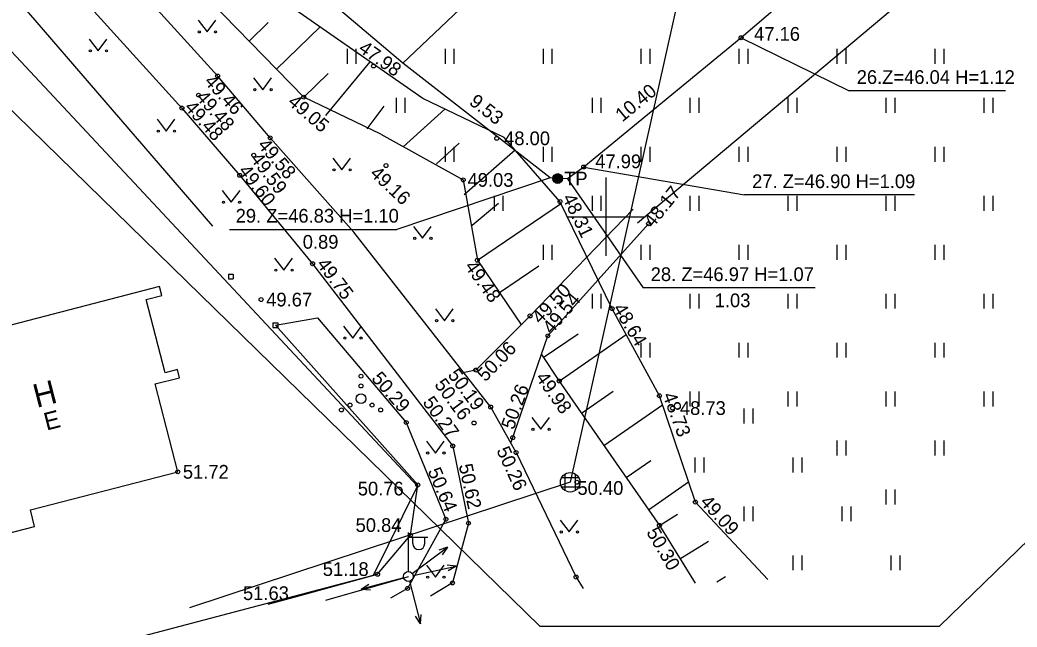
# Model space of a CAD drawing. Extents: x 642747 to 644424, y 6457048 to 6458238.
# Drawn here: x 644020.1 to 644071, y 6457529.1 to 6457560 of the extents above; entities that cross this region are included whole.
import ezdxf

# ---------------------------------------------------------------- set-up
doc = ezdxf.new("R2010")
doc.units = 0
for name, color, linetype in [('AED', 7, 'Continuous'), ('DKAEV', 7, 'Continuous'), ('DTRASS', 7, 'Continuous'), ('HALJASTUS', 7, 'Continuous'), ('HOONE', 7, 'Continuous'), ('JOONSIDE', 7, 'Continuous'), ('KOORDPUNKT', 7, 'Continuous'), ('KORGUS', 7, 'Continuous'), ('KPKAABEL', 7, 'Continuous'), ('MOOTPIIR', 7, 'Continuous'), ('MPOHULIIN', 7, 'Continuous'), ('PIIR', 7, 'Continuous'), ('POST', 7, 'Continuous'), ('RELJEEF', 7, 'Continuous'), ('TEE', 7, 'Continuous'), ('VORK', 7, 'Continuous')]:
    doc.layers.add(name, color=color, linetype=linetype)

msp = doc.modelspace()

# ---------------------------------------------------------------- linework, layer by layer
at = {"layer": 'AED'}
for p, q in [((644030.734, 6457547.073), (644030.734, 6457546.823)), ((644030.734, 6457547.073), (644030.984, 6457547.073)), ((644030.984, 6457547.073), (644030.984, 6457546.823)), ((644030.734, 6457546.823), (644030.984, 6457546.823)), ((644033.01, 6457544.59), (644033.01, 6457544.34)), ((644033.01, 6457544.59), (644033.26, 6457544.59)), ((644033.26, 6457544.59), (644033.26, 6457544.34)), ((644033.01, 6457544.34), (644033.26, 6457544.34))]:
    msp.add_line(p, q, dxfattribs=at)
for points in [[(644038.347, 6457531.745), (644040.021, 6457533.742), (644040.399, 6457536.307), (644033.135, 6457544.465)], [(644032.769, 6457530.227), (644034.097, 6457530.581), (644038.347, 6457531.745)]]:
    msp.add_lwpolyline(points, dxfattribs=at)
at = {"layer": 'DKAEV'}
for p, q in [((644047.925, 6457536.009), (644047.925, 6457536.875)), ((644048.425, 6457536.875), (644048.425, 6457536.009)), ((644047.742, 6457536.692), (644048.608, 6457536.692)), ((644048.608, 6457536.192), (644047.742, 6457536.192))]:
    msp.add_line(p, q, dxfattribs=at)
msp.add_circle((644048.175, 6457536.442), 0.5, dxfattribs=at)
at = {"layer": 'DTRASS'}
for points in [[(644054.394, 6457564.336), (644048.175, 6457536.442)], [(644048.175, 6457536.442), (644028.741, 6457530.029)]]:
    msp.add_lwpolyline(points, dxfattribs=at)
at = {"layer": 'HALJASTUS'}
for p, q in [((644029.185, 6457560.042), (644029.648, 6457559.436)), ((644029.648, 6457559.436), (644030.094, 6457560.042)), ((644023.626, 6457559.073), (644024.09, 6457558.466)), ((644024.09, 6457558.466), (644024.535, 6457559.073)), ((644036.79, 6457558.569), (644036.79, 6457557.807)), ((644037.245, 6457558.569), (644037.245, 6457557.807)), ((644041.79, 6457558.569), (644041.79, 6457557.807)), ((644042.245, 6457558.569), (644042.245, 6457557.807)), ((644046.79, 6457558.569), (644046.79, 6457557.807)), ((644047.245, 6457558.569), (644047.245, 6457557.807)), ((644051.79, 6457558.569), (644051.79, 6457557.807)), ((644052.245, 6457558.569), (644052.245, 6457557.807)), ((644056.79, 6457558.569), (644056.79, 6457557.807)), ((644057.245, 6457558.569), (644057.245, 6457557.807)), ((644061.79, 6457558.569), (644061.79, 6457557.807)), ((644062.245, 6457558.569), (644062.245, 6457557.807)), ((644066.79, 6457558.569), (644066.79, 6457557.807)), ((644067.245, 6457558.569), (644067.245, 6457557.807)), ((644032.022, 6457557.094), (644032.486, 6457556.487)), ((644032.486, 6457556.487), (644032.931, 6457557.094)), ((644039.29, 6457556.069), (644039.29, 6457555.307)), ((644039.745, 6457556.069), (644039.745, 6457555.307)), ((644049.29, 6457556.069), (644049.29, 6457555.307)), ((644049.745, 6457556.069), (644049.745, 6457555.307)), ((644054.29, 6457556.069), (644054.29, 6457555.307)), ((644054.745, 6457556.069), (644054.745, 6457555.307)), ((644059.29, 6457556.069), (644059.29, 6457555.307)), ((644059.745, 6457556.069), (644059.745, 6457555.307)), ((644064.29, 6457556.069), (644064.29, 6457555.307)), ((644064.745, 6457556.069), (644064.745, 6457555.307)), ((644069.29, 6457556.069), (644069.29, 6457555.307)), ((644069.745, 6457556.069), (644069.745, 6457555.307)), ((644027.092, 6457554.977), (644027.555, 6457554.37)), ((644027.555, 6457554.37), (644028.001, 6457554.977)), ((644041.79, 6457553.569), (644041.79, 6457552.807)), ((644042.245, 6457553.569), (644042.245, 6457552.807)), ((644046.79, 6457553.569), (644046.79, 6457552.807)), ((644047.245, 6457553.569), (644047.245, 6457552.807)), ((644051.79, 6457553.569), (644051.79, 6457552.807)), ((644052.245, 6457553.569), (644052.245, 6457552.807)), ((644056.79, 6457553.569), (644056.79, 6457552.807)), ((644057.245, 6457553.569), (644057.245, 6457552.807)), ((644061.79, 6457553.569), (644061.79, 6457552.807)), ((644062.245, 6457553.569), (644062.245, 6457552.807)), ((644066.79, 6457553.569), (644066.79, 6457552.807)), ((644067.245, 6457553.569), (644067.245, 6457552.807)), ((644036.061, 6457552.998), (644036.524, 6457552.391)), ((644036.524, 6457552.391), (644036.97, 6457552.998)), ((644030.421, 6457551.346), (644030.884, 6457550.739)), ((644030.884, 6457550.739), (644031.33, 6457551.346)), ((644044.29, 6457551.069), (644044.29, 6457550.307)), ((644044.745, 6457551.069), (644044.745, 6457550.307)), ((644049.29, 6457551.069), (644049.29, 6457550.307)), ((644049.745, 6457551.069), (644049.745, 6457550.307)), ((644054.29, 6457551.069), (644054.29, 6457550.307)), ((644054.745, 6457551.069), (644054.745, 6457550.307)), ((644059.29, 6457551.069), (644059.29, 6457550.307)), ((644059.745, 6457551.069), (644059.745, 6457550.307)), ((644064.29, 6457551.069), (644064.29, 6457550.307)), ((644064.745, 6457551.069), (644064.745, 6457550.307)), ((644069.29, 6457551.069), (644069.29, 6457550.307)), ((644069.745, 6457551.069), (644069.745, 6457550.307)), ((644040.181, 6457549.503), (644040.645, 6457548.897)), ((644040.645, 6457548.897), (644041.09, 6457549.503)), ((644046.79, 6457548.569), (644046.79, 6457547.807)), ((644047.245, 6457548.569), (644047.245, 6457547.807)), ((644051.79, 6457548.569), (644051.79, 6457547.807)), ((644052.245, 6457548.569), (644052.245, 6457547.807)), ((644056.79, 6457548.569), (644056.79, 6457547.807)), ((644057.245, 6457548.569), (644057.245, 6457547.807)), ((644061.79, 6457548.569), (644061.79, 6457547.807)), ((644062.245, 6457548.569), (644062.245, 6457547.807)), ((644066.79, 6457548.569), (644066.79, 6457547.807)), ((644067.245, 6457548.569), (644067.245, 6457547.807)), ((644033.095, 6457547.878), (644033.558, 6457547.272)), ((644033.558, 6457547.272), (644034.004, 6457547.878)), ((644049.29, 6457546.069), (644049.29, 6457545.307)), ((644049.745, 6457546.069), (644049.745, 6457545.307)), ((644054.29, 6457546.069), (644054.29, 6457545.307)), ((644054.745, 6457546.069), (644054.745, 6457545.307)), ((644059.29, 6457546.069), (644059.29, 6457545.307)), ((644059.745, 6457546.069), (644059.745, 6457545.307)), ((644064.29, 6457546.069), (644064.29, 6457545.307)), ((644064.745, 6457546.069), (644064.745, 6457545.307)), ((644069.29, 6457546.069), (644069.29, 6457545.307)), ((644069.745, 6457546.069), (644069.745, 6457545.307)), ((644041.3, 6457545.299), (644041.764, 6457544.692)), ((644041.764, 6457544.692), (644042.209, 6457545.299)), ((644036.615, 6457544.411), (644037.078, 6457543.804)), ((644037.078, 6457543.804), (644037.524, 6457544.411)), ((644051.79, 6457543.569), (644051.79, 6457542.807)), ((644052.245, 6457543.569), (644052.245, 6457542.807)), ((644056.79, 6457543.569), (644056.79, 6457542.807)), ((644057.245, 6457543.569), (644057.245, 6457542.807)), ((644061.79, 6457543.569), (644061.79, 6457542.807)), ((644062.245, 6457543.569), (644062.245, 6457542.807)), ((644066.79, 6457543.569), (644066.79, 6457542.807)), ((644067.245, 6457543.569), (644067.245, 6457542.807)), ((644054.29, 6457541.069), (644054.29, 6457540.307)), ((644054.745, 6457541.069), (644054.745, 6457540.307)), ((644059.29, 6457541.069), (644059.29, 6457540.307)), ((644059.745, 6457541.069), (644059.745, 6457540.307)), ((644064.29, 6457541.069), (644064.29, 6457540.307)), ((644064.745, 6457541.069), (644064.745, 6457540.307)), ((644069.29, 6457541.069), (644069.29, 6457540.307)), ((644069.745, 6457541.069), (644069.745, 6457540.307)), ((644057.043, 6457540.21), (644057.043, 6457539.449)), ((644057.498, 6457540.21), (644057.498, 6457539.449)), ((644046.212, 6457539.756), (644046.675, 6457539.149)), ((644046.675, 6457539.149), (644047.121, 6457539.756)), ((644040.844, 6457538.541), (644041.308, 6457537.934)), ((644041.308, 6457537.934), (644041.753, 6457538.541)), ((644061.79, 6457538.569), (644061.79, 6457537.807)), ((644062.245, 6457538.569), (644062.245, 6457537.807)), ((644066.79, 6457538.569), (644066.79, 6457537.807)), ((644067.245, 6457538.569), (644067.245, 6457537.807)), ((644054.543, 6457537.71), (644054.543, 6457536.949)), ((644054.998, 6457537.71), (644054.998, 6457536.949)), ((644059.543, 6457537.71), (644059.543, 6457536.949)), ((644059.998, 6457537.71), (644059.998, 6457536.949)), ((644064.29, 6457536.069), (644064.29, 6457535.307)), ((644064.745, 6457536.069), (644064.745, 6457535.307)), ((644057.043, 6457535.21), (644057.043, 6457534.449)), ((644057.498, 6457535.21), (644057.498, 6457534.449)), ((644062.043, 6457535.21), (644062.043, 6457534.449)), ((644062.498, 6457535.21), (644062.498, 6457534.449)), ((644047.658, 6457534.514), (644048.121, 6457533.907)), ((644048.121, 6457533.907), (644048.567, 6457534.514)), ((644059.543, 6457532.71), (644059.543, 6457531.949)), ((644059.998, 6457532.71), (644059.998, 6457531.949)), ((644064.543, 6457532.71), (644064.543, 6457531.949)), ((644064.998, 6457532.71), (644064.998, 6457531.949)), ((644040.844, 6457532.206), (644041.308, 6457531.6)), ((644041.308, 6457531.6), (644041.753, 6457532.206))]:
    msp.add_line(p, q, dxfattribs=at)
for points in [[(643947.897, 6457637.828), (643981.209, 6457604.157), (643998.602, 6457584.178), (644020.537, 6457560.412), (644029.925, 6457549.512)], [(644033.135, 6457544.465), (644035.273, 6457544.831), (644039.808, 6457539.494), (644041.835, 6457534.557), (644039.876, 6457531.024), (644038.999, 6457530.534)]]:
    msp.add_lwpolyline(points, dxfattribs=at)
for centre, radius in [((644029.247, 6457559.436), 0.055), ((644030.076, 6457559.436), 0.055), ((644023.689, 6457558.466), 0.055), ((644024.517, 6457558.466), 0.055), ((644032.085, 6457556.487), 0.055), ((644032.914, 6457556.487), 0.055), ((644027.154, 6457554.37), 0.055), ((644027.983, 6457554.37), 0.055), ((644036.123, 6457552.391), 0.055), ((644036.952, 6457552.391), 0.055), ((644030.483, 6457550.739), 0.055), ((644031.312, 6457550.739), 0.055), ((644040.244, 6457548.897), 0.055), ((644041.073, 6457548.897), 0.055), ((644033.157, 6457547.272), 0.055), ((644033.986, 6457547.272), 0.055), ((644041.362, 6457544.692), 0.055), ((644042.191, 6457544.692), 0.055), ((644036.677, 6457543.804), 0.055), ((644037.506, 6457543.804), 0.055), ((644037.503, 6457541.86), 0.1), ((644037.503, 6457541.36), 0.1), ((644037.503, 6457540.71), 0.25), ((644036.938, 6457540.385), 0.1), ((644038.068, 6457540.385), 0.1), ((644036.503, 6457540.135), 0.1), ((644038.503, 6457540.135), 0.1), ((644046.274, 6457539.149), 0.055), ((644047.103, 6457539.149), 0.055), ((644040.907, 6457537.934), 0.055), ((644041.736, 6457537.934), 0.055), ((644047.72, 6457533.907), 0.055), ((644048.549, 6457533.907), 0.055), ((644040.907, 6457531.6), 0.055), ((644041.736, 6457531.6), 0.055)]:
    msp.add_circle(centre, radius, dxfattribs=at)
at = {"layer": 'HOONE'}
msp.add_lwpolyline([(644013.799, 6457542.952), (644016.351, 6457533.035), (644020.845, 6457534.191), (644020.627, 6457535.04), (644028.15, 6457536.976), (644026.996, 6457541.46), (644028.247, 6457541.782), (644028.141, 6457542.195), (644027.509, 6457542.032), (644026.546, 6457545.777), (644027.332, 6457545.979), (644027.214, 6457546.436)], close=True, dxfattribs=at)
at = {"layer": 'KOORDPUNKT'}
for p, q in [((644039.639, 6457557.844), (644043.422, 6457561.433)), ((644056.896, 6457559.139), (644062.413, 6457556.431)), ((644070.393, 6457556.431), (644062.413, 6457556.431)), ((644048.865, 6457552.537), (644057.076, 6457551.11)), ((644047.155, 6457551.979), (644039.329, 6457549.348)), ((644048.039, 6457551.927), (644051.901, 6457546.366)), ((644065.755, 6457551.11), (644057.076, 6457551.11)), ((644030.79, 6457549.348), (644039.329, 6457549.348)), ((644060.686, 6457546.366), (644051.901, 6457546.366))]:
    msp.add_line(p, q, dxfattribs=at)
for points in [[(644056.896, 6457559.139), (644056.896, 6457559.139), (644056.896, 6457559.139)], [(644039.639, 6457557.844), (644039.639, 6457557.844), (644039.639, 6457557.844)], [(644048.865, 6457552.537), (644048.865, 6457552.537), (644048.865, 6457552.537)], [(644047.155, 6457551.979), (644047.155, 6457551.979), (644047.155, 6457551.979)], [(644048.039, 6457551.927), (644048.039, 6457551.927), (644048.039, 6457551.927)]]:
    msp.add_lwpolyline(points, dxfattribs=at)
at = {"layer": 'KORGUS'}
for centre in [(644056.896, 6457559.139), (644038.143, 6457557.695), (644030.182, 6457557.185), (644029.208, 6457556.205), (644034.582, 6457556.103), (644028.361, 6457555.547), (644032.867, 6457554.025), (644044.429, 6457554.004), (644032.028, 6457553.143), (644038.777, 6457552.611), (644048.865, 6457552.537), (644031.31, 6457552.113), (644042.718, 6457551.88), (644047.656, 6457550.775), (644052.179, 6457549.642), (644035.03, 6457547.601), (644043.439, 6457547.779), (644032.404, 6457545.77), (644050.317, 6457545.304), (644046.128, 6457544.934), (644047.037, 6457543.918), (644043.358, 6457542.172), (644047.617, 6457541.613), (644052.731, 6457540.858), (644044.12, 6457540.285), (644053.399, 6457540.231), (644039.808, 6457539.494), (644043.27, 6457539.468), (644045.245, 6457538.721), (644042.186, 6457538.294), (644045.414, 6457537.961), (644028.15, 6457536.976), (644040.399, 6457536.307), (644048.521, 6457536.445), (644054.567, 6457535.432), (644041.835, 6457534.557), (644042.986, 6457534.354), (644052.729, 6457534.244), (644040.021, 6457533.742), (644038.347, 6457531.745), (644048.476, 6457531.604), (644039.876, 6457531.024), (644042.17, 6457531.304)]:
    msp.add_circle(centre, 0.1, dxfattribs=at)
at = {"layer": 'KPKAABEL'}
msp.add_lwpolyline([(644103.079, 6457652.715), (644111.131, 6457630.665), (644117.872, 6457612.305), (644117.831, 6457611.89), (644117.527, 6457611.592), (644112.751, 6457607.616), (644102.693, 6457600.124), (644092.698, 6457590.582), (644078.192, 6457577.561), (644066.524, 6457567.369), (644056.896, 6457559.139), (644048.865, 6457552.537), (644048.039, 6457551.927), (644047.155, 6457551.979), (644039.639, 6457557.844), (644029.553, 6457566.384), (644016.901, 6457577.396), (644002.145, 6457590.823), (643989.718, 6457602.415), (643976.894, 6457615.305), (643965.556, 6457626.702)], dxfattribs=at)
at = {"layer": 'MOOTPIIR'}
msp.add_lwpolyline([(643525.446, 6457467.559), (643537.447, 6457435.458), (643944.848, 6457628.51), (644046.626, 6457529.09), (644067.022, 6457529.09), (644138.408, 6457598.401), (644075.1, 6457775.215), (644046.02, 6457752.582), (644092.466, 6457611.94), (644070.657, 6457576.375), (644041.981, 6457570.717), (643942.223, 6457662.862)], close=True, dxfattribs=at)
at = {"layer": 'MPOHULIIN'}
for p, q in [((644040.118, 6457531.782), (644041.921, 6457533.128)), ((644041.921, 6457533.128), (644041.47, 6457532.978)), ((644041.921, 6457533.128), (644041.648, 6457532.739)), ((644040.163, 6457531.686), (644042.363, 6457532.157)), ((644042.363, 6457532.157), (644041.891, 6457532.209)), ((644042.363, 6457532.157), (644041.952, 6457531.917)), ((644039.682, 6457531.565), (644037.51, 6457530.977)), ((644037.51, 6457530.977), (644037.907, 6457531.238)), ((644039.984, 6457531.392), (644040.535, 6457529.21)), ((644037.51, 6457530.977), (644037.985, 6457530.95)), ((644040.535, 6457529.21), (644040.28, 6457529.612)), ((644040.535, 6457529.21), (644040.57, 6457529.684))]:
    msp.add_line(p, q, dxfattribs=at)
at = {"layer": 'PIIR'}
msp.add_lwpolyline([(644002.28, 6457577.05), (644015.62, 6457525.76), (644038.14, 6457531.7), (644040.39, 6457536.24)], close=True, dxfattribs=at)
at = {"layer": 'POST'}
for p, q in [((644039.918, 6457531.882), (644039.918, 6457533.882)), ((644039.918, 6457533.632), (644040.918, 6457533.632)), ((644040.145, 6457533.311), (644040.145, 6457533.632)), ((644040.757, 6457533.311), (644040.757, 6457533.632)), ((644035.708, 6457530.426), (644039.918, 6457531.632)), ((644039.918, 6457531.632), (644039.918, 6457531.632))]:
    msp.add_line(p, q, dxfattribs=at)
for centre, radius in [((644047.54, 6457551.95), 0.25), ((644047.54, 6457551.95), 0.225), ((644047.54, 6457551.95), 0.2), ((644047.54, 6457551.95), 0.175), ((644047.54, 6457551.95), 0.15), ((644047.54, 6457551.95), 0.125), ((644047.54, 6457551.95), 0.1), ((644047.54, 6457551.95), 0.075), ((644047.54, 6457551.95), 0.05), ((644047.54, 6457551.95), 0.025), ((644039.921, 6457531.632), 0.25)]:
    msp.add_circle(centre, radius, dxfattribs=at)
msp.add_arc((644040.451, 6457533.311), 0.306, 180, 0, dxfattribs=at)
at = {"layer": 'RELJEEF'}
for p, q in [((644031.793, 6457558.97), (644032.767, 6457559.918)), ((644033.187, 6457557.536), (644035.41, 6457559.698)), ((644035.703, 6457555.17), (644037.977, 6457557.902)), ((644034.582, 6457556.103), (644035.83, 6457557.317)), ((644037.817, 6457554.491), (644038.691, 6457555.64)), ((644039.656, 6457553.572), (644041.771, 6457555.499)), ((644041.358, 6457552.697), (644042.507, 6457553.754)), ((644042.772, 6457551.14), (644045.368, 6457553.412)), ((644043.177, 6457549.575), (644044.518, 6457550.688)), ((644043.439, 6457547.779), (644047.731, 6457550.688)), ((644044.561, 6457546.124), (644046.575, 6457547.489)), ((644046.805, 6457542.812), (644048.583, 6457544.018)), ((644047.617, 6457541.613), (644051.034, 6457543.984)), ((644048.757, 6457539.97), (644050.376, 6457541.093)), ((644049.897, 6457538.327), (644052.886, 6457540.4)), ((644051.037, 6457536.683), (644052.295, 6457537.556)), ((644052.177, 6457535.04), (644054.22, 6457536.458)), ((644052.729, 6457534.244), (644053.656, 6457534.816)), ((644053.779, 6457532.542), (644055.241, 6457533.443)), ((644055.662, 6457531.353), (644056.106, 6457531.627))]:
    msp.add_line(p, q, dxfattribs=at)
for points in [[(644040.652, 6457556.032), (644032.787, 6457561.533), (644024.267, 6457567.686), (644013.888, 6457578.559), (644004.095, 6457588.275), (643993.471, 6457598.922), (643984.908, 6457608.291), (643982.871, 6457611.083), (643985.277, 6457614.077)], [(644038.518, 6457554.209), (644034.582, 6457556.103), (644028.426, 6457562.43), (644026.5, 6457562.219), (644014.667, 6457575.068), (644002.176, 6457588.096), (643989.067, 6457601.802), (643980.842, 6457610.819), (643983.167, 6457613.454)], [(644058.255, 6457531.481), (644054.567, 6457535.432), (644052.731, 6457540.858), (644050.317, 6457545.304), (644047.656, 6457550.775), (644044.814, 6457554.05), (644040.652, 6457556.032)], [(644038.518, 6457554.209), (644042.718, 6457551.88), (644043.439, 6457547.779), (644045.69, 6457544.457)], [(644046.706, 6457542.958), (644047.617, 6457541.613), (644052.729, 6457534.244), (644054.546, 6457531.298)]]:
    msp.add_lwpolyline(points, dxfattribs=at)
at = {"layer": 'TEE'}
for points in [[(644045.414, 6457537.961), (644044.12, 6457540.285), (644037.139, 6457549.214), (644032.867, 6457554.025), (644030.182, 6457557.185), (644018.058, 6457570.518), (644006.462, 6457582.723), (643994.161, 6457595.954), (643981.396, 6457609.563), (643968.526, 6457623.391), (643955.996, 6457636.272), (643954.769, 6457637.545)], [(643953.164, 6457635.53), (643954.521, 6457634.202), (643966.746, 6457621.258), (643979.497, 6457607.902), (643992.403, 6457593.942), (644004.789, 6457581.012), (644016.437, 6457568.699), (644028.361, 6457555.547), (644031.31, 6457552.113), (644035.03, 6457547.601), (644042.186, 6457538.294), (644042.986, 6457534.354), (644042.17, 6457531.304), (644041.041, 6457530.634)], [(644051.619, 6457549.694), (644075.076, 6457569.399), (644100.273, 6457592.468), (644111.741, 6457604.69), (644121.185, 6457609.883)], [(644051.388, 6457550.392), (644046.128, 6457544.934), (644043.358, 6457542.172), (644042.694, 6457542.026)], [(644045.163, 6457538.482), (644047.037, 6457543.918), (644052.179, 6457549.642)], [(644045.414, 6457537.961), (644048.476, 6457531.604), (644048.847, 6457531.018)]]:
    msp.add_lwpolyline(points, dxfattribs=at)
at = {"layer": 'VORK'}
for p, q in [((644050, 6457552), (644050, 6457548)), ((644048, 6457550), (644052, 6457550))]:
    msp.add_line(p, q, dxfattribs=at)

# ---------------------------------------------------------------- texts
at = {"layer": 'HOONE'}
for s, height, p in [('H', 1.2, (644020.949, 6457540.236)), ('E', 0.9, (644021.451, 6457539.077))]:
    msp.add_text(s, height=height, rotation=14.4301, dxfattribs=at).set_placement(p)
at = {"layer": 'JOONSIDE'}
for s, rotation, p in [('10.40', 39.4224, (644050.84, 6457554.814)), ('9.53', 322.0338, (644042.977, 6457555.77))]:
    msp.add_text(s, height=0.7, rotation=rotation, dxfattribs=at).set_placement(p)
for s, p in [('0.89', (644034.528, 6457548.367)), ('1.03', (644055.551, 6457545.382))]:
    msp.add_text(s, height=0.7, dxfattribs=at).set_placement(p)
at = {"layer": 'KOORDPUNKT'}
for s, p in [('26.Z=46.04 H=1.12', (644062.798, 6457556.781)), ('27. Z=46.90 H=1.09', (644057.461, 6457551.46)), ('29. Z=46.83 H=1.10', (644031.105, 6457549.698)), ('28. Z=46.97 H=1.07', (644052.286, 6457546.716))]:
    msp.add_text(s, height=0.7, dxfattribs=at).set_placement(p)
at = {"layer": 'KORGUS'}
for s, p in [('47.16', (644057.561, 6457558.985)), ('48.00', (644044.804, 6457553.654)), ('47.99', (644049.455, 6457552.477)), ('49.03', (644042.939, 6457551.53)), (' 49.67', (644032.404, 6457545.42)), ('48.73', (644053.774, 6457539.881)), (' 51.72', (644028.15, 6457536.626)), (' 50.76', (644037.077, 6457535.77)), (' 50.40', (644048.287, 6457535.801)), (' 50.84', (644036.965, 6457533.906)), (' 51.18', (644035.29, 6457531.66)), (' 51.63', (644031.219, 6457530.43))]:
    msp.add_text(s, height=0.7, dxfattribs=at).set_placement(p)
for s, rotation, p in [(' 47.98', 324.7279, (644037.114, 6457558.619)), (' 49.46', 312.0089, (644029.29, 6457557.071)), (' 49.48', 311.1233, (644028.867, 6457556.271)), (' 49.05', 319.3217, (644033.521, 6457555.95)), (' 49.48', 312.0096, (644028.278, 6457555.745)), (' 49.58', 310.4067, (644032.021, 6457553.834)), (' 49.59', 307.022, (644031.659, 6457553.164)), (' 49.60', 307.5317, (644031.055, 6457552.536)), (' 49.16', 316.8309, (644037.723, 6457552.324)), (' 48.17', 50.9538, (644052.233, 6457549.184)), (' 48.31', 295.532, (644047.649, 6457551.208)), (' 49.75', 307.0235, (644035.05, 6457547.775)), (' 49.48', 305.1671, (644042.618, 6457547.674)), (' 49.50', 46.3315, (644046.472, 6457544.295)), (' 49.54', 49.3487, (644047.058, 6457543.764)), (' 48.64', 300.8276, (644050.206, 6457545.547)), (' 50.06', 45.8718, (644043.668, 6457541.352)), (' 50.29', 310.9601, (644037.829, 6457541.913)), (' 50.19', 306.4753, (644041.743, 6457542.129)), (' 49.98', 305.0469, (644046.239, 6457541.994)), (' 50.16', 306.3684, (644041.063, 6457541.634)), (' 50.26', 70.0041, (644045.198, 6457538.843)), (' 50.27', 305.8218, (644040.465, 6457540.728)), (' 48.73', 290.2783, (644052.795, 6457541.134)), (' 50.26', 294.6013, (644044.291, 6457538.31)), (' 50.64', 292.8101, (644040.792, 6457537.259)), (' 50.62', 282.174, (644042.431, 6457537.566)), (' 49.09', 312.177, (644054.587, 6457535.596)), (' 50.30', 300.1515, (644051.912, 6457534.116))]:
    msp.add_text(s, height=0.7, rotation=rotation, dxfattribs=at).set_placement(p)
at = {"layer": 'POST'}
msp.add_text('TP', height=0.7, dxfattribs=at).set_placement((644047.866, 6457551.597))

doc.saveas('drawing.dxf')
